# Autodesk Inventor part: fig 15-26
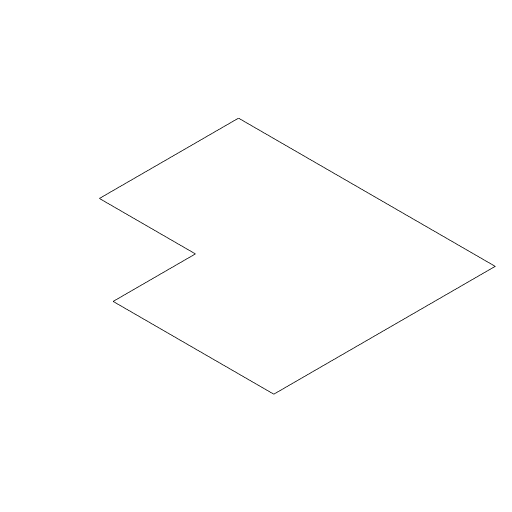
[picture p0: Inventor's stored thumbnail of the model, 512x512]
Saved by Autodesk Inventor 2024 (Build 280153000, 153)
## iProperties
Created: 2005-03
Part Number: fig 15-26
Document SubType Name: Sheet Metal
Designer: CADCIM
Manufacturer: Standard
Standards Organization: Custom
Density: 1 g/cm^3
Sheet Metal Rule: Default
Material: Generic
Appearance: Default
Author: CADCIM
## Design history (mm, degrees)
sketch "Sketch1"
  geometry: L1 (29.25, 32.25)-(-19.875, 32.25); L2 (-19.875, 32.25)-(-19.875, 5.625); L3 (-19.875, 5.625)-(-1.5, 5.625); L4 (-1.5, 5.625)-(-1.5, -10.125); L5 (-1.5, -10.125)-(29.25, -10.125); L6 (29.25, -10.125)-(29.25, 32.25)
  constraints: 12 end point, 4 parallel, 1 horizontal, 1 perpendicular
body "Solid1"
other parameters: "Thickness" = 0.5, "BendRadius" = 0.5 (= Thickness), "BendReliefWidth" = 0.5 (= Thickness), "BendReliefDepth" = 0.25 (= 0.5 x Thickness), "CornerReliefSize" = 2 (= 4 x Thickness), "SeamGap" = 0.01, "MinimumRemnant" = 1 (= 2 x Thickness), "TransitionRadius" = 0.5 (= BendRadius), "JacobiRadiusSize" = 0.5 (= Thickness), "GapSize" = 0.5 (= Thickness), "d0" = 0.5 (= BendRadius)
